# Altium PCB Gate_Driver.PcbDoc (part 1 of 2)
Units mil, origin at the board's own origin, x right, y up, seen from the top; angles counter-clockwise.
Board outline 1574.8 x 1574.8 mil, 2 copper layers (Top Layer, Bottom Layer), stack 62 mil thick; 111 components, 52 nets, 273 pads, 84 vias.
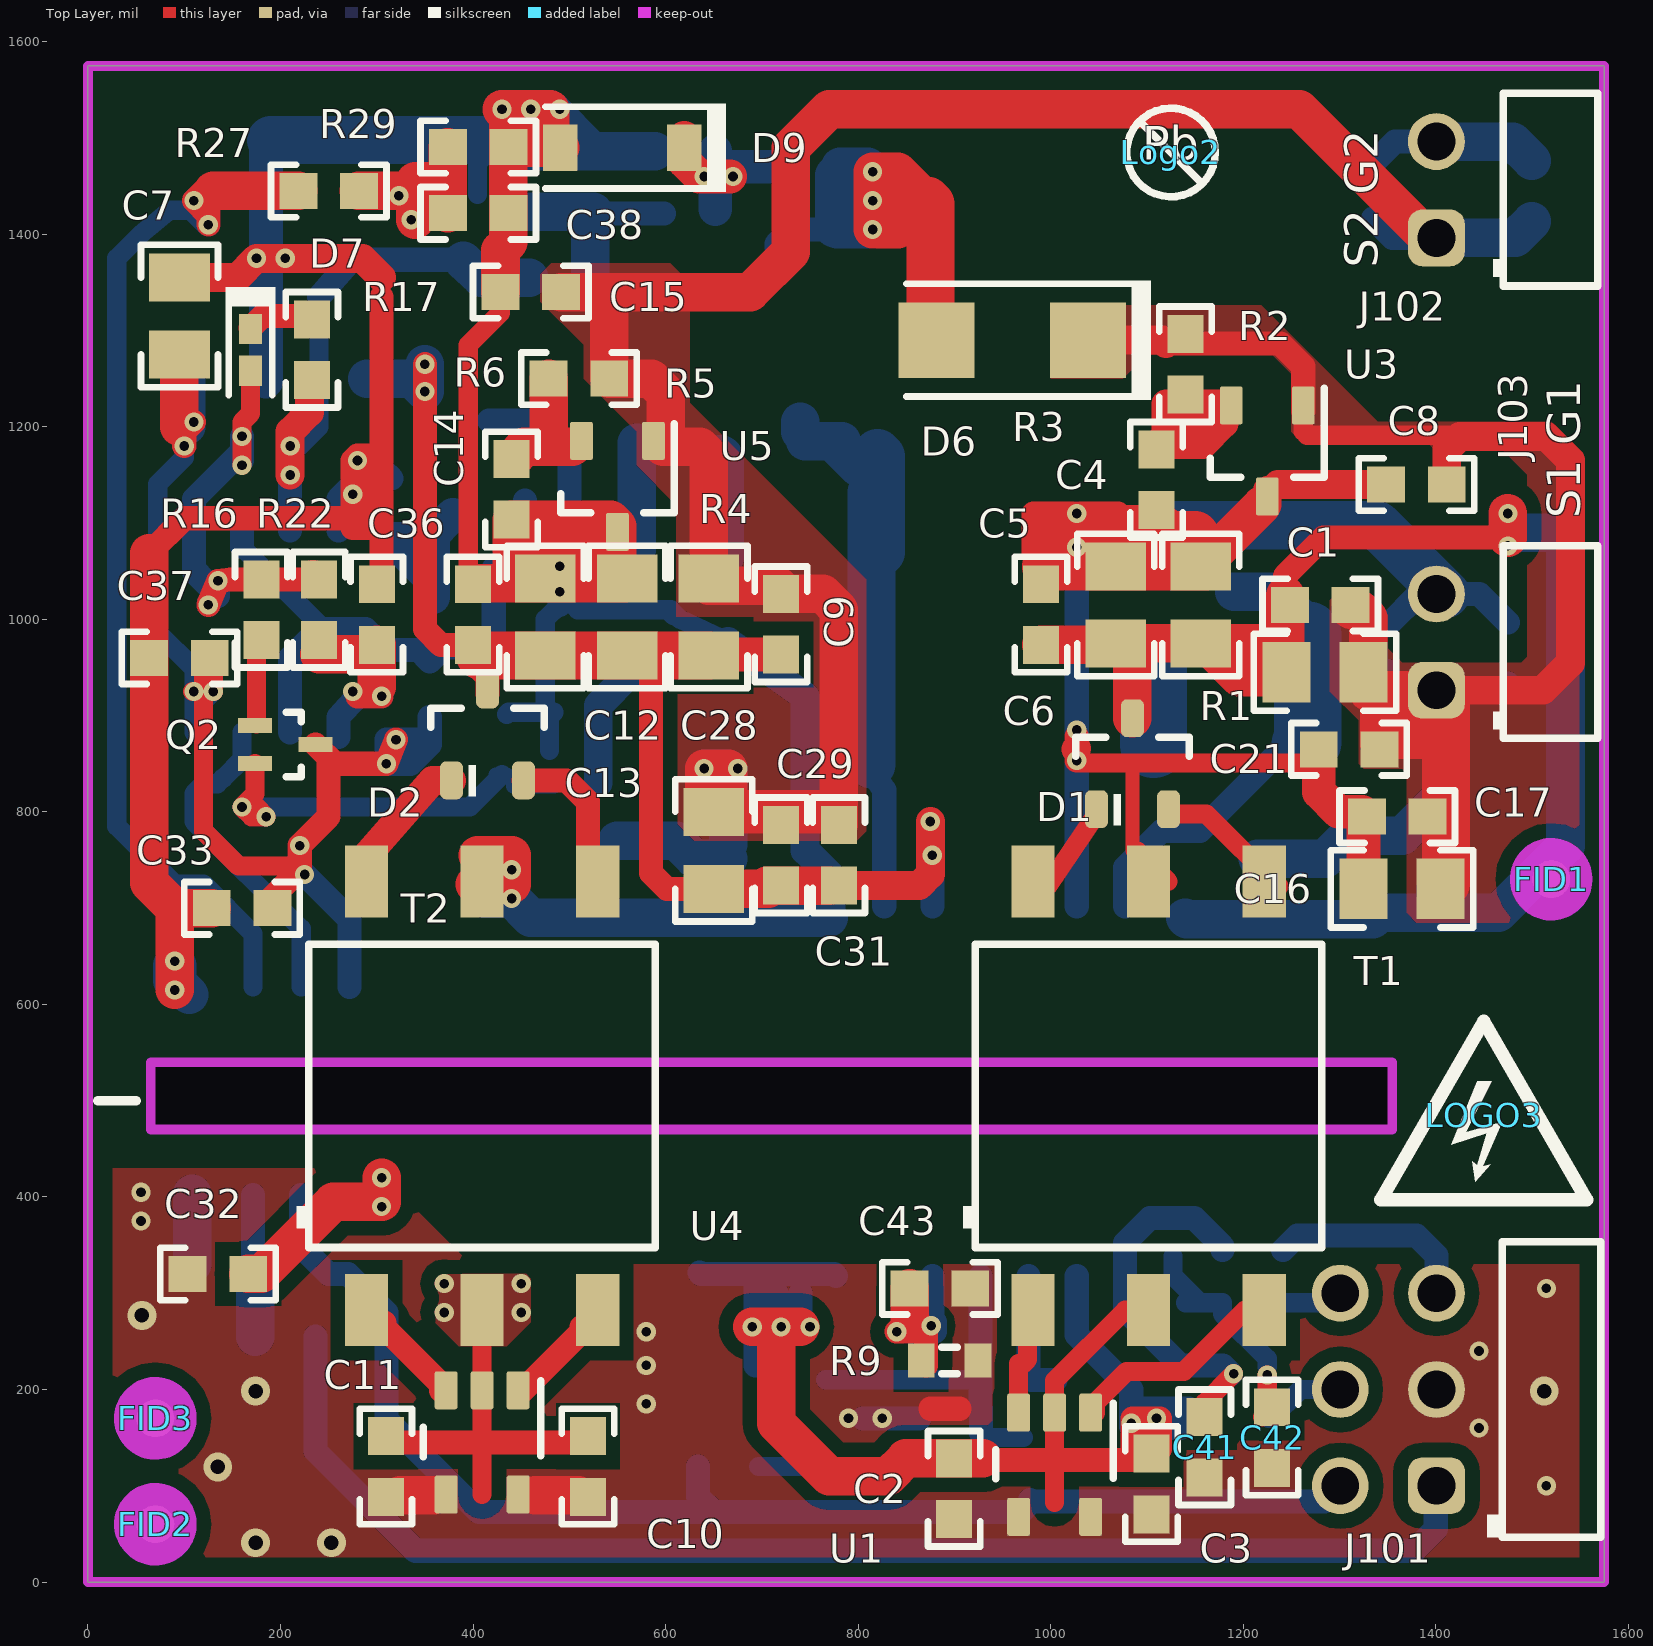
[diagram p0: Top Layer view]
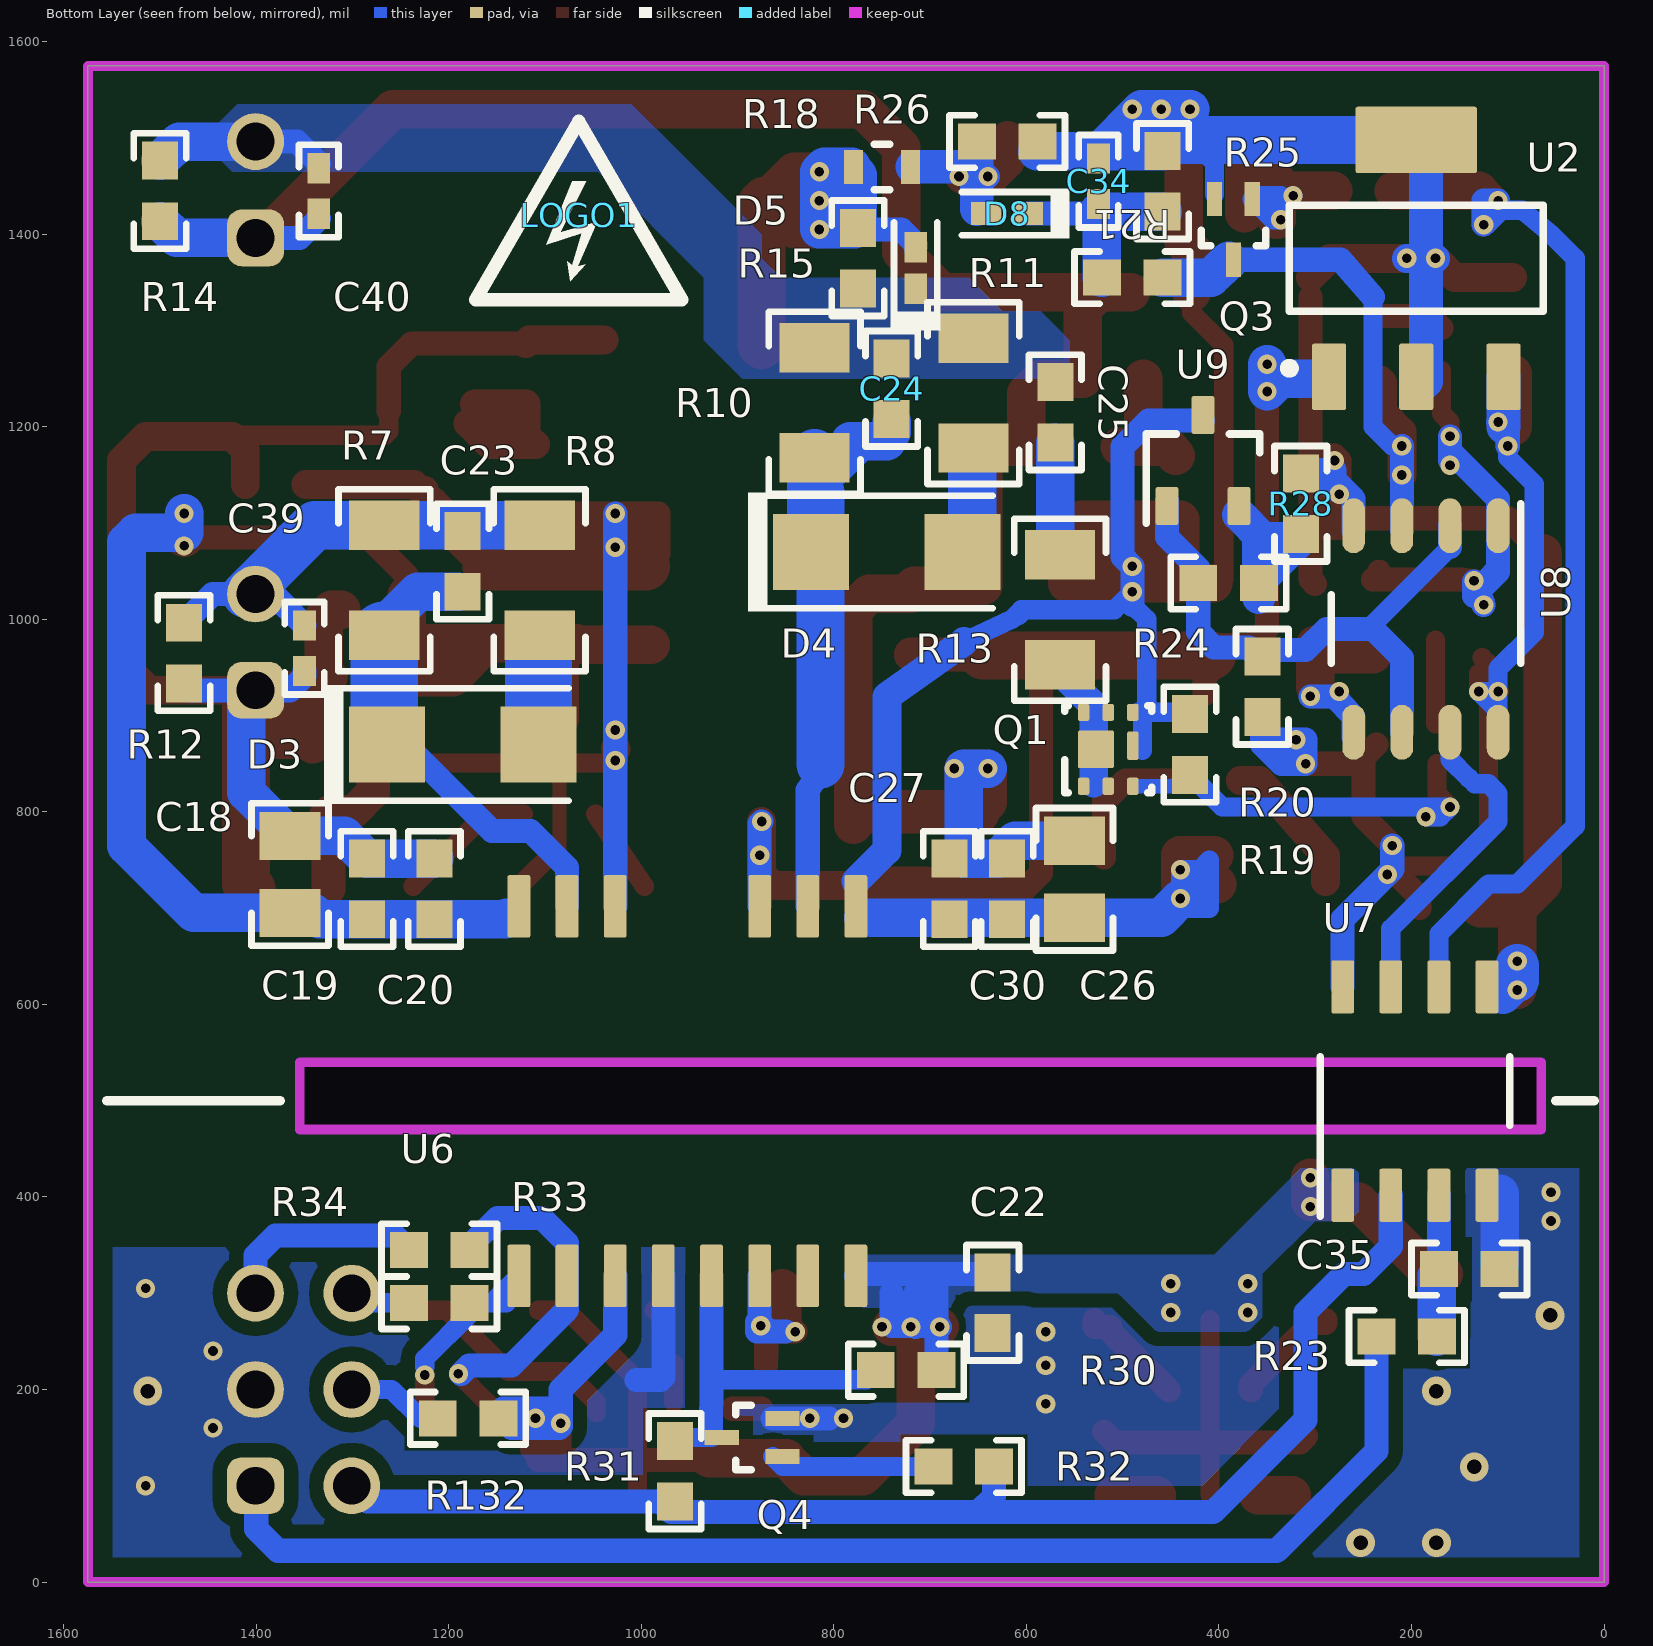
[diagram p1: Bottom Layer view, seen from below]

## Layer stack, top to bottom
Top Solder: solder mask 0.4, Solder Resist, Dk 3.5
Top Layer: signal copper 1.4
Dielectric 1: core 59.2, FR-4, Dk 4.8
Bottom Layer: signal copper 1.4
Bottom Solder: solder mask 0.4, Solder Resist, Dk 3.5

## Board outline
0,0 1574.8,0 1574.8,1574.8 0,1574.8
cut-out: 65,540 1355,540 1355,470 65,470

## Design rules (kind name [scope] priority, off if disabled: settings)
AcuteAngle [All] p1: minimum=3.00000000000000E+0001 checktracksonly=FALSE
AssemblyTestPointUsage [All] p1: valid=2
BoardOutlineClearance BoardOutlineClearance_MountingHoles [OnCopper and InComponentClass('Mounting Holes')] p1: gap=40 ignorepadtopadclearanceinfootprint=FALSE
BoardOutlineClearance BoardOutlineClearance_Poly [OnCopper and IsPoly] p2: gap=25 ignorepadtopadclearanceinfootprint=FALSE
BoardOutlineClearance [OnCopper and Not InComponentClass('Logo') and not InComponentClass('FiducialMark') and not InRegion(1000,500,4000,800) and not InPoly] p3: gap=0 ignorepadtopadclearanceinfootprint=FALSE
Clearance Clearance_Keepouts [((IsTrack Or IsArc) And Not InPoly) And IsFree and IsKeepOut vs ((IsTrack Or IsArc) And Not InPoly) And IsFree and IsKeepOut] p1: gap=0 ignorepadtopadclearanceinfootprint=FALSE
Clearance Clearance_Poly [InPolygon] p2: gap=15 ignorepadtopadclearanceinfootprint=FALSE
Clearance Clearance_FiducialMark [IsKeepOut and InComponentClass('FiducialMark') vs IsPad and InComponentClass('FiducialMark')] p3: gap=0 ignorepadtopadclearanceinfootprint=FALSE
Clearance [All vs not InComponent('D7')and not InComponent('Q1') and not InComponent('D8')and not InComponent('D5') and not InComponent('U4')and not InComponent('U1')] p4: gap=15 ignorepadtopadclearanceinfootprint=FALSE
ComponentClearance ComponentClearance_MountingHoles_FiducialMarks [InComponentClass('Mounting Holes') vs InComponentClass('FiducialMark')] p1: gap=50 collisioncheckmode=3 verticalgap=10 showdistances=FALSE
ComponentClearance ComponentClearance_Shunt [InComponentClass('Header') vs InComponentClass('Shunt')] p2: gap=0 collisioncheckmode=3 verticalgap=0 showdistances=FALSE
ComponentClearance ComponentClearance_Logo [InComponentClass('Logo')] p3: gap=50 collisioncheckmode=3 verticalgap=10 showdistances=FALSE
ComponentClearance ComponentClearance_ScrewToNut [(HasFootprint('NY PMS 440 0025 PH')) vs (HasFootprint('Keystone_1902C'))] p4: gap=5 collisioncheckmode=3 verticalgap=10 showdistances=FALSE
ComponentClearance ComponentClearance_MountingHoles [InComponentClass('Mounting Holes')] p5: gap=250 collisioncheckmode=3 verticalgap=100000 showdistances=FALSE
ComponentClearance ComponentClearance_SmallPassives [HasFootprint('0201*') or HasFootprint('0402*') or HasFootprint('0508') or HasFootprint('0603*') or HasFootprint('0612') or HasFootprint('0805*') or HasFootprint('0815*') or HasFootprint('0830*') or HasFootprint('1206*') or HasFootprint('1210*') or HasFootprint('1808*') or HasFootprint('1812*') or HasFootprint('1825*') or HasFootprint('2010*') or HasFootprint('2220*') or HasFootprint('2225*') or HasFootprint('2512*') or HasFootprint('2728*') or HasFootprint('3518*') vs HasFootprint('0201*') or HasFootprint('0402*') or HasFootprint('0508') or HasFootprint('0603*') or HasFootprint('0612') or HasFootprint('0805*') or HasFootprint('0815*') or HasFootprint('0830*') or HasFootprint('1206*') or HasFootprint('1210*') or HasFootprint('1808*') or HasFootprint('1812*') or HasFootprint('1825*') or HasFootprint('2010*') or HasFootprint('2220*') or HasFootprint('2225*') or HasFootprint('2512*') or HasFootprint('2728*') or HasFootprint('3518*')] p6: gap=14.96 collisioncheckmode=3 verticalgap=10 showdistances=FALSE
ComponentClearance ComponentClearance_THtoSMT [IsThruComponent vs IsSMTComponent] p7: gap=27.56 collisioncheckmode=3 verticalgap=30 showdistances=FALSE
ComponentClearance ComponentClearance_THtoTH [IsThruComponent vs IsThruComponent] p8: gap=30 collisioncheckmode=3 verticalgap=30 showdistances=FALSE
ComponentClearance [All] p9: gap=19.68 collisioncheckmode=3 verticalgap=10 showdistances=FALSE
DiffPairsRouting [All] p1: maxlimit=100 minlimit=10 mostfreqgap=10 toplayer_minwidth=15 toplayer_maxwidth=15 toplayer_prefwidth=15 bottomlayer_minwidth=15 bottomlayer_maxwidth=15 bottomlayer_prefwidth=15 maxuncoupledlength=1000
FabricationTestPointUsage TestPointUsage [All] p1: valid=2 allowmultiple=FALSE
FabricationTestpoint Testpoint [All] p1: side=3 testpointundercomponent=TRUE minsize=40 maxsize=100 preferedsize=60 minholesize=0 maxholesize=40 preferedholesize=32 testpointgrid=1 allowsidetop=TRUE allowsidebottom=TRUE usegrid=TRUE gridtolerance=0.01
FanoutControl Fanout_LCC [IsLCC] p1: bgadir=Out bgaviamode=Centered fanoutstyle=Auto fanoutdirection=Alternating viagrid=1 // Fanout_LCC (Default Rule)
FanoutControl Fanout_BGA [IsBGA] p2: bgadir=Out bgaviamode=Centered fanoutstyle=Auto fanoutdirection=Alternating viagrid=1 // Fanout_BGA (Default Rule)
FanoutControl Fanout_Default [All] p4: bgadir=Out bgaviamode=Centered fanoutstyle=Auto fanoutdirection=Alternating viagrid=1 // Fanout_Default (Default Rule)
FanoutControl Fanout_Small [(CompPinCount < 5)] p5: bgadir=Out bgaviamode=Centered fanoutstyle=Auto fanoutdirection=OutThenIn viagrid=1 // Fanout_Small (Default Rule)
HoleSize [All] p1: absolutevalues=TRUE maxlimit=251 minlimit=7.87 maxpercent=80.000 minpercent=20.000
MinimumAnnularRing MinimumAnnularRing_ThermalPadVias [IsVia and InAnyComponent] p1: minimumring=5.91
MinimumAnnularRing [All] p2: minimumring=5
MinimumSolderMaskSliver MinimumSolderMaskSliver_Logo [InComponentClass('Logo') vs InComponentClass('Logo')] p1: minsoldermaskwidth=0.7
MinimumSolderMaskSliver [All] p2: minsoldermaskwidth=2
PlaneConnect [All] p1: planeconnectstyle=Relief reliefexpansion=10 reliefentries=4 reliefconductorwidth=10 reliefairgap=10
PolygonConnect [All] p1: connectstyle=Direct reliefconductorwidth=10 reliefentries=4 polygonreliefangle="90 Angle" airgapwidth=10
RoutingVias ThermalPadVias [IsVia and InAnyComponent] p1: holewidth=7.87 width=19.68 viastyle="Through Hole" minholewidth=7.87 minwidth=19.68 maxholewidth=12.99 maxwidth=23.62
RoutingVias [All] p2: holewidth=16 width=34 viastyle="Through Hole" minholewidth=7.87 minwidth=20 maxholewidth=40 maxwidth=65
SilkToBoardRegionClearance [Not ((IsComment or IsDesignator) And (Hide <> 'False')) and not InRegion(1000,500,4000,800)] p1:
SilkToSilkClearance SilkToSilkClearance_Pb-FreeLogo [(HasFootprint('Pb-Free_Overlay_Medium') OR HasFootprint('Pb-Free_Overlay_Small')) vs (HasFootprint('Pb-Free_Overlay_Medium') OR HasFootprint('Pb-Free_Overlay_Small'))] p1: silktosilkclearance=0
SilkToSilkClearance [All] p2: silktosilkclearance=4
SilkToSolderMaskClearance SilkToComponentPadClearance [(IsPad or IsFill or IsRegion) and InAnycomponent] p1: minsilkscreentomaskgap=0 clearancetoexposedcopper=TRUE
SilkToSolderMaskClearance "Silk to Solder Mask Opening" [All] p2: minsilkscreentomaskgap=0 clearancetoexposedcopper=FALSE
SolderMaskExpansion [All] p1: expansion=1.97
Width [All] p1: maxlimit=100 minlimit=6 preferedwidth=10 checkconnectedcopper=TRUE
15 further rules are at their usual default settings.

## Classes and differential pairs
component class FiducialMark: FID1 FID2 FID3
component class Gate_Driver_Hardware: !PCB FID1 FID2 FID3 LOGO1 Logo2 LOGO3
component class Gate_Driver: C1 C2 C3 C4 C5 C6 C7 C8 C9 C10 C11 C12 C13 C14 C15 C16 C17 C18 C19 C20 C21 C22 C23 C24 C25 C26 C27 C28 C29 C30 C31 C32 C33 C34 C35 C36 C37 C38 C39 C40 C41 C42 C43 D1 D2 D3 D4 D5 D6 D7 D8 D9 J101 J102 J103 Q1 Q2 Q3 Q4 R1 R2 R3 R4 R5 R6 R7 R8 R9 R10 R11 R12 R13 R14 R15 R16 R17 R18 R19 R20 R21 R22 R23 R24 R25 R26 R27 R28 R29 R30 R31 R32 R33 R34 R132 T1 T2 U1 U2 U3 U4 U5 U6 U7 U8 U9
component class Header: J101 J102 J103

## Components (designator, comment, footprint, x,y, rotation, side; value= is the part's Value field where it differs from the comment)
C1 "CGA3E2X7R1E104K080AA" 0603 1280,1015 r0 top value=0.1uF
C2 "GRT188C81A106ME13D" 0603 899.69,96.81 r270 top value=10uF
C3 "CGA3E2X7R1E104K080AA" 0603 1104.69,101.81 r270 top value=0.1uF
C4 "GRT21BR61H475KE13L" 0805_HV 1067.6,1015 r90 top value=4.7uF
C5 "GRT21BR61H475KE13L" 0805_HV 1155.83,1015 r90 top value=4.7uF
C6 "CGA3E2X7R1E104K080AA" 0603 990,1005 r90 top value=0.1uF
C7 "GRT21BR61H475KE13L" 0805_HV 95,1315 r90 top value=4.7uF
C8 "CGA3E2X7R1E104K080AA" 0603 1380,1140 r180 top value=0.1uF
C9 "CGA3E2X7R1E104K080AA" 0603 720,995 r90 top value=0.1uF
C10 "GRT188C81A106ME13D" 0603 519.37,120 r270 top value=10uF
C11 "CGA3E2X7R1E104K080AA" 0603 309.37,120 r270 top value=0.1uF
C12 "GRT21BR61H475KE13L" 0805_HV 560,1002.44 r90 top value=4.7uF
C13 "GRT21BR61H475KE13L" 0805_HV 475,1002.44 r90 top value=4.7uF
C14 "CGA3E2X7R1E104K080AA" 0603 400,1005 r90 top value=0.1uF
C15 "CGA3E2X7R1E104K080AA" 0603 460,1340 r180 top value=0.1uF
C16 "GRT21BR61H475KE13L" 0805_HV 1365,720 r180 top value=4.7uF
C17 "CGA3E2X7R1E104K080AA" 0603 1360,795 r180 top value=0.1uF
C18 "GRT21BR61H475KE13L" 0805_HV 1365,735 r270 bottom value=4.7uF
C19 "CGA3E2X7R1E104K080AA" 0603 1285,720 r270 bottom value=0.1uF
C20 "CGA3E2C0G1H103J080AA" 0603 1215,720 r270 bottom value=0.01uF
C21 "CGA3E2C0G1H103J080AA" 0603 1310,865 r180 top value=0.01uF
C22 "CGA3E2X7R1E104K080AA" 0603 635,290 r270 bottom value=0.1uF
C23 "CGA3E2X7R1E104K080AA" 0603 1185.55,1060.18 r90 bottom value=0.1uF
C24 "CGA3E2X7R1E104K080AA" 0603 740,1239.51 r90 bottom value=0.1uF
C25 "CGA3E2X7R1E104K080AA" 0603 570,1215 r270 bottom value=0.1uF
C26 "GRT21BR61H475KE13L" 0805_HV 550,730 r90 bottom value=4.7uF
C27 "CGA3E2X7R1E104K080AA" 0603 680,720 r90 bottom value=0.1uF
C28 "GRT21BR61H475KE13L" 0805_HV 650,760 r90 top value=4.7uF
C29 "CGA3E2X7R1E104K080AA" 0603 720,755 r90 top value=0.1uF
C30 "CGA3E2C0G1H103J080AA" 0603 620,720 r90 bottom value=0.01uF
C31 "CGA3E2C0G1H103J080AA" 0603 780,755 r90 top value=0.01uF
C32 "CGA3E2X7R1E104K080AA" 0603 135,320 r180 top value=0.1uF
C33 "CGA3E2X7R1E104K080AA" 0603 160,700 r180 top value=0.1uF
C34 "GRM1555C1H270JA01D" 0402 525,1455 r90 bottom value=27pF
C35 "CGA3E2NP01H101J080AA" 0603 140,325 r180 bottom value=100pF
C36 "GCM1885C1H471JA16D" 0603 300,1005 r90 top value=470pF
C37 "CGA3E2X7R1E104K080AA" 0603 95,960 r180 top value=0.1uF
C38 "GCM1885C2A101JA16D" 0603 405.28,1421.89 r0 top value=100pF
C39 "GCM155R71H102KA37D" 0402 1350,970 r270 bottom value=1000pF
C40 "GCM155R71H102KA37D" 0402 1335,1445 r270 bottom value=1000pF
C41 "GCM1885C2A101JA16D" 0603 1160,140 r270 top value=100pF
C42 "GCM1885C2A101JA16D" 0603 1230,150 r270 top value=100pF
C43 "GCM1885C2A101JA16D" 0603 885,305 r0 top value=100pF
D1 "BAV70-E3-08" SOT-23 1085,850 r90 top value=70V
D2 "BAV70-E3-08" SOT-23 415,880 r90 top value=70V
D3 "MBRA340T3G" SMA 1185.55,870 r180 bottom value=40V
D4 "MBRA340T3G" SMA 745,1070 r180 bottom value=40V
D5 "1N4148X-TP" SOD-523 715,1365 r90 bottom value=75V
D6 "BYG23T-M3/TR" SMA 960,1290 r180 top value=1300V
D7 "1N4148X-TP" SOD-523 168.8,1280 r270 top value=75V
D8 "1N4148X-TP" SOD-523 620,1421.46 r0 bottom value=75V
D9 "BZT52C5V1-G3-08" SOD-123 555,1490 r180 top value=5.1V
FID1 "Fiducial" Fiducial10-20 1520,730 r0 top
FID2 "Fiducial" Fiducial10-20 70,60 r0 top
FID3 "Fiducial" Fiducial10-20 70,170 r0 top
J101 "90122-0763" Molex_90122-0763 1350.82,200 r180 top
J102 "90121-0762" Molex_90121-0762 1400.63,1446.3 r180 top
J103 "90121-0762" Molex_90121-0762 1400.63,976.3 r180 top
LOGO1 "DANGER HIGH VOLTAGE" IEC_HighVoltage_Small 1065,1420 r180 bottom
Logo2 "Pb-Free Symbol" Pb-Free_Overlay_Small 1125,1485 r0 top
LOGO3 "DANGER HIGH VOLTAGE" IEC_HighVoltage_Small 1450,485 r0 top
Q1 "CSD17313Q2" DQK0006C 515,865 r90 bottom value=30V
Q2 "MMBT3904T-7-F" SOT-523 205,870 r0 top value="40 V"
Q3 "MMBT3904T-7-F" SOT-523 385,1405 r270 bottom value="40 V"
Q4 "MMBT3904T-7-F" SOT-523 885,150 r0 bottom value="40 V"
R1 "CRCW08054K70JNEA" 0805_HV 1285,945 r180 top value=4.7k
R2 "RT0603DRE073K01L" 0603 1140,1265 r90 top value=3.01k
R3 "RT0603DRE074K99L" 0603 1110,1145 r90 top value=4.99k
R4 "CRCW08054K70JNEA" 0805_HV 645,1002.44 r270 top value=4.7k
R5 "RT0603DRE073K01L" 0603 510,1250 r0 top value=3.01k
R6 "RT0603DRE074K99L" 0603 440,1135 r90 top value=4.99k
R7 "CRCW12065R11FKEA" 1206 1267.05,1040.67 r90 bottom value=5.11
R8 "CRM1206-JW-1R0ELF" 1206 1105.55,1040.67 r90 bottom value=1.0
R9 "1" J1-0603 895,230 r0 top
R10 "CRCW12065R11FKEA" 1206 820,1225 r90 bottom value=5.11
R11 "CRM1206-JW-1R0ELF" 1206 655,1235 r90 bottom value=1.0
R12 "CRCW060310K0FKEA" 0603 1475,965 r90 bottom value=10.0k
R13 "CRCW120627R0JNEA" 1206 565,1010 r90 bottom value=27
R14 "CRCW060310K0FKEA" 0603 1500,1445 r90 bottom value=10.0k
R15 "RC0603JR-075K1L" 0603 775,1375 r270 bottom value=5.1k
R16 "RCA06031K00JNEA" 0603 180,1010 r270 top value=1.0k
R17 "RCA06031K00JNEA" 0603 232.5,1280 r270 top value=1.0k
R18 "TNPW060310K0BEEA" TNPW0603 750,1470 r0 bottom value=10.0k
R19 "RCA06031K00JNEA" 0603 430,869.96 r90 bottom value=1.0k
R20 "RC0603JR-075K1L" 0603 355,930 r270 bottom value=5.1k
R21 "CRCW06031K00FKEA" 0603 490,1355 r0 bottom value=1.00k
R22 "RC0603JR-072K2L" 0603 240,1010 r270 top value=2.2k
R23 "RC0603JR-075K1L" 0603 205,255 r180 bottom value=5.1k
R24 "RT0603DRE072KL" 0603 390,1037.8 r0 bottom value=2.00k
R25 "RC0603JR-075K1L" 0603 458.5,1455 r270 bottom value=5.1k
R26 "RC0603JR-075K1L" 0603 620,1496.46 r0 bottom value=5.1k
R27 "RCA06031K00JNEA" 0603 250,1445 r0 top value=1.0k
R28 "RT0603DRE0710KL" 0603 315,1120 r270 bottom value=10.0k
R29 "RC0603JR-0715KL" 0603 405.28,1490.59 r180 top value=15k
R30 "RC0603JR-075K1L" 0603 725,220 r180 bottom value=5.1k
R31 "CRCW06030000Z0EA" 0603 965,115 r90 bottom value=0
R32 "RC0603JR-075K1L" 0603 665,120 r180 bottom value=5.1k
R33 "CRCW06030000Z0EA" 0603 1210,290 r0 bottom value=0
R34 "CRCW06030000Z0EA" 0603 1210,345 r0 bottom value=0
R132 "CRCW06030000Z0EA" 0603 1180,170 r180 bottom value=0
T1 "3.9:1" Wurth_750342879 1101.77,505 r90 top value=50uH
T2 "3.9:1" Wurth_750342879 409.37,505 r90 top value=50uH
U1 "SN6501QDBVRQ1" DBV0005A_N 1004.06,121.81 r270 top
U2 "TPS7B6950QDCYRQ1" DCY0004A_N 195,1375 r90 bottom
U3 "TL431AQDBZRQ1" DBZ0003A_N 1225,1175 r270 top
U4 "SN6501QDBVRQ1" DBV0005A_N 409.37,145 r270 top
U5 "TL431AQDBZRQ1" DBZ0003A_N 550,1138.07 r270 top
U6 "UCC21530QDWKRQ1" DWK0014A 952.13,510 r90 bottom
U7 "ISO7721QDRQ1" D0008B_HV 196.5,510 r90 bottom
U8 "LMV762QMA" D0008A_N 185,990 r270 bottom
U9 "TL431AQDBZRQ1" DBZ0003A_N 416.57,1165 r90 bottom

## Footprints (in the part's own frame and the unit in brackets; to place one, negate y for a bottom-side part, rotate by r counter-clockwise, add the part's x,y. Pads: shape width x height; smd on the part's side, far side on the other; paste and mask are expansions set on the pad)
0402 [mm] "0402 from SM-752 data"
  rect 0.8x0.6 smd: 1(-0.6,0) 2(0.6,0)
  silkscreen extent -1.22,-0.52 1.22,0.52, body extent -0.55,-0.3 0.55,0.3, height 0.6
0603 [mm] "0603 from SM-752 data"
  rect 1x0.95 smd: 1(-0.8,0) 2(0.8,0)
  silkscreen extent -1.52,-0.69 1.52,0.69, body extent -0.87,-0.47 0.87,0.47, height 1
0805_HV [mil] "0805 with 30mil clearance between pads"
  rect 50x63 smd: 1(-40,0) 2(40,0)
  silkscreen extent -74,-40 74,40, body extent -43,-29 43,29, height 57
1206 [mm] "1206 from SM-752 data"
  rect 1.3x1.85 smd: 1(-1.45,0) 2(1.45,0)
  silkscreen extent -2.4,-1.21 2.4,1.21, body extent -1.7,-0.9 1.7,0.9, height 1.35
D0008A_N [mm] "SOIC, 8-Leads, Body 4.9x3.9mm, Pitch 1.27mm, IPC Medium Density"
  oval 1.45x0.6 smd: 1(-2.725,1.905) 2(-2.725,0.635) 3(-2.725,-0.635) 4(-2.725,-1.905) 5(2.725,-1.905) 6(2.725,-0.635) 7(2.725,0.635) 8(2.725,1.905)
  silkscreen extent -3.3,-2.5 0.9,2.5, body extent -3,-2.45 3,2.45, height 1.63
D0008B_HV [mm] "SOIC, 8-Leads, Body 4.9x3.9mm, Pitch 1.27mm, HV / Isolation option"
  rrect17% 1.4x0.6 smd: 1(-2.75,1.905) 2(-2.75,0.635) 3(-2.75,-0.635) 4(-2.75,-1.905) 5(2.75,-1.905) 6(2.75,-0.635) 7(2.75,0.635) 8(2.75,1.905)
  silkscreen extent -3.3,-2.5 0.9,2.5, body extent -3,-2.45 3,2.45, height 1.63
DBV0005A_N [mm] "SOT23, 5-Leads, Body 2.9x1.6mm, Pitch 0.95mm, Lead Span 2.8mm, IPC Medium Density"
  rrect17% 1x0.6 smd: 1(-1.375,0.95) 2(-1.375,0) 3(-1.375,-0.95) 4(1.375,-0.95) 5(1.375,0.95)
  silkscreen extent -1.63,-1.55 0.38,1.55, body extent -1.42,-1.46 1.42,1.46, height 1.09
DBZ0003A_N [mm] "SOT23, 3-Leads, Body 2.9x1.3mm, Pitch 0.95mm, Lead Span 2.4mm, IPC Medium Density"
  rrect17% 1x0.6 smd: 1(-1.2,0.95) 2(-1.2,-0.95) 3(1.2,0)
  silkscreen extent -1.65,-1.5 0.7,1.5, body extent -1.26,-1.46 1.26,1.46, height 0.98
DCY0004A_N [mm] "SOT223/SC73, 4-Leads, Body 6.5x3.5mm, Pitch 2.3mm, Lead Span 7mm, IPC Medium Density"
  rrect11% 1.75x0.9 smd: 1(-3.125,2.3) 2(-3.125,0) 3(-3.125,-2.3)
  rrect6% 1.75x3.2 smd: 4(3.125,0)
  silkscreen extent -3.02,-3.35 1.4,3.48, body extent -3.48,-3.25 3.48,3.25, height 1.68
DQK0006C [mm] "WSON"
  rrect12% 0.9x0.86 on Bottom Paste: 0(0,0.325)
  rrect34% 0.7x0.29 on Bottom Paste: 0(0.095,-0.65)
  rrect33% 0.45x0.3 smd: 1(-0.975,0.65) 2(-0.975,0) 3(-0.975,-0.65) 4(0.975,-0.65) 5(0.975,0) 6(0.975,0.65)
  rrect33% 0.75x0.3 smd paste-0.15: 7(0.095,-0.65)
  rrect11% 1x0.95 smd paste-0.5: 8(0,0.325)
  silkscreen extent -1.15,-1.15 1.15,1.15, body extent -1,-1 1,1, height 0.82
DWK0014A [mm] "SOIC-14"
  rrect17% 1.65x0.6 smd: 1(-4.875,4.445) 2(-4.875,3.175) 3(-4.875,1.905) 4(-4.875,0.635) 5(-4.875,-0.635) 6(-4.875,-1.905) 7(-4.875,-3.175) 8(-4.875,-4.445) 9(4.875,-4.445) 10(4.875,-3.175) 11(4.875,-1.905) 14(4.875,1.905) 15(4.875,3.175) 16(4.875,4.445)
  body extent -5.17,-5.15 5.17,5.15, height 2.59
Fiducial10-20 [mm]
  round 1 smd mask+0.5: 1(0,0)
  Top Layer keep-out circle w1.178: c0,0 r0.5
IEC_HighVoltage_Small [mil]
  silkscreen extent -107,-88 107,97
J1-0603 [mm] "Chip Resistor, Body 1.6x0.8mm, IPC High Density"
  rect 0.7x0.9 smd: 1(-0.75,0) 2(0.75,0)
  silkscreen extent -0.2,-0.35 0.2,0.35, body extent -0.85,-0.48 0.85,0.48, height 0.9
Molex_90121-0762 [mm] "Header, 2.54mm, 2x1, R/A, TH"
  rrect50% 1.5x1.5 hole 1: 1(0,1.27)
  round 1.5 hole 1: 2(0,-1.27)
  silkscreen extent -4.25,-2.54 -1.5,2.54, body extent -11.01,-2.54 0.31,2.54, height 3.6
Molex_90122-0763 [mm] "Header, 2.54mm, 3x2, R/A, TH"
  rrect50% 1.5x1.5 hole 1: 1(-1.27,2.54)
  round 1.5 hole 1: 2(1.27,2.54) 3(-1.27,0) 4(1.27,0) 5(-1.27,-2.54) 6(1.27,-2.54)
  silkscreen extent -5.6,-3.9 -2.6,3.9, body extent -12.27,-3.81 1.57,3.81, height 6.35
Pb-Free_Overlay_Small [mil]
  silkscreen extent -46,-46 46,46
SMA [mm] "Molded Diode, 2-Leads, Body 4.3x2.6mm, IPC Medium Density, based on OnSemi component dimensions and land pattern"
  rect 2x2 smd: 1(-2,0) 2(2,0)
  silkscreen extent -3.66,-1.57 2.79,1.57, body extent -2.6,-1.3 2.6,1.3, height 2.42
SOD-123 [mm] "On Semi recommended land pattern"
  rect 0.915x1.22 smd: 1(-1.637,0) 2(1.637,0)
  silkscreen extent -2.74,-1.17 2.03,1.17, body extent -1.93,-0.9 1.93,0.9, height 1.35
SOD-523 [mm] "NXP Semiconductor recommended land pattern, nominal STEP model"
  rect 0.8x0.6 smd paste-0.05: 1(-0.55,0) 2(0.55,0)
  silkscreen extent -1.65,-0.66 1.2,0.66, body extent -0.8,-0.4 0.8,0.4, height 0.72
SOT-23 [mm] "SOT23, 3-Leads, Body 2.9x1.3mm, Pitch 0.95mm, Lead Span 2.5mm, IPC Medium Density"
  rrect50% 1x0.6 smd: 1(-1.2,0.95) 2(-1.2,-0.95) 3(1.2,0)
  silkscreen extent -1.63,-1.5 0.7,1.5, body extent -1.16,-1.45 1.21,1.45, height 1
SOT-523 [mm] "From Diodes Inc datasheet component parameters"
  rect 0.9x0.4 smd: 1(-0.8,0.5) 2(-0.8,-0.5) 3(0.8,0)
  silkscreen extent 0.02,-0.85 0.42,0.85, body extent -0.8,-0.8 0.8,0.8, height 0.79
TNPW0603 [mm] "Vishay"
  rect 0.5x0.9 smd: 1(-0.75,0) 2(0.75,0)
  silkscreen extent -0.2,-0.6 0.2,0.6, body extent -0.85,-0.47 0.85,0.47, height 0.55
Wurth_750342879 [mm] "SMD, 6-Leads, Body 9.14x8mm, Pitch 3.05mm"
  rect 1.9x1.14 smd: 1(-5.655,3.05) 2(-5.655,0) 3(-5.655,-3.05) 4(5.655,-3.05) 5(5.655,0) 6(5.655,3.05)
  silkscreen extent -4,-4.57 4,4.9, body extent -6.35,-4.57 6.35,4.57, height 7.83

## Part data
C1 C3 C6 C8 C9 C11 C14 C15 C17 C19 C22 C23 C24 C25 C27 C29 C32 C33 C37: "CAP, CERM, 0.1 礔, 25 V,+/- 10%, X7R, AEC-Q200 Grade 1, 0603", Cap_Case=0603, Manufacturer=TDK, Supplier Part Number 1=445-5667-1-ND, TempCo=X7R, Tolerance_%=10, Value2=25V, ValueDisplayed=0.1μF
C2 C10: "CAP, CERM, 10 礔, 10 V,+/- 20%, X6S, AEC-Q200 Grade 2, 0603", Cap_Case=0603, Manufacturer=MuRata, Supplier Part Number 1=490-12283-1-ND, TempCo=X6S, Tolerance_%=20, Value2=10V, ValueDisplayed=10μF
C4 C5 C7 C12 C13 C16 C18 C26 C28: "CAP, CERM, 4.7 礔, 50 V,+/- 10%, X5R, AEC-Q200 Grade 3, 0805", Cap_Case=0805, Manufacturer=MuRata, Supplier Part Number 1=490-12394-1-ND, TempCo=X5R, Tolerance_%=10, Value2=50V, ValueDisplayed=4.7μF
C20 C21 C30 C31: "CAP, CERM, 0.01 礔, 50 V,+/- 5%, C0G/NP0, AEC-Q200 Grade 1, 0603", Cap_Case=0603, Manufacturer=TDK, Supplier Part Number 1=445-6916-1-ND, TempCo=C0G/NP0, Tolerance_%=5, Value2=50V, ValueDisplayed=0.01μF
C34: "CAP, CERM, 27 pF, 50 V,+/- 5%, C0G/NP0, 0402", Cap_Case=0402, Manufacturer=MuRata, Supplier Part Number 1=14T3294, TempCo=C0G/NP0, Tolerance_%=5, Value2=50V, ValueDisplayed=27pF
C35: "CAP, CERM, 100 pF, 50 V,+/- 5%, C0G/NP0, AEC-Q200 Grade 0, 0603", Cap_Case=0603, Manufacturer=TDK, Supplier Part Number 1=445-12386-1-ND, TempCo=C0G/NP0, Tolerance_%=5, Value2=50V, ValueDisplayed=100pF
C36: "CAP, CERM, 470 pF, 50 V,+/- 5%, C0G/NP0, AEC-Q200 Grade 1, 0603", Cap_Case=0603, Manufacturer=MuRata, Supplier Part Number 1=490-4965-1-ND, TempCo=C0G/NP0, Tolerance_%=5, Value2=50V, ValueDisplayed=470pF
C38 C41 C42 C43: "CAP, CERM, 100 pF, 100 V,+/- 5%, C0G/NP0, AEC-Q200 Grade 1, 0603", Cap_Case=0603, Manufacturer=MuRata, Supplier Part Number 1=490-4771-1-ND, TempCo=C0G/NP0, Tolerance_%=5, Value2=100V, ValueDisplayed=100pF
C39 C40: "CAP, CERM, 1000 pF, 50 V,+/- 10%, X7R, AEC-Q200 Grade 1, 0402", Cap_Case=0402, Manufacturer=MuRata, Supplier Part Number 1=490-4761-1-ND, TempCo=X7R, Tolerance_%=10, Value2=50V, ValueDisplayed=1000pF
D1 D2: "Diode, Switching, 70 V, 0.25 A, AEC-Q101, SOT-23", Manufacturer=Vishay-Semiconductor, Supplier Part Number 1=BAV70-E3-08CT-ND, Value1=0.25A, Value2=1.25V
D3 D4: "Diode, Schottky, 40 V, 3 A, SMA", Manufacturer="ON Semiconductor", Supplier Part Number 1=1431078, Value1=3A, Value2=0.415V
D5 D7 D8: "Diode, Switching, 75 V, 0.3 A, SOD-523", Manufacturer="Micro Commercial Components", Supplier Part Number 1=1N4148XTPMSCT-ND, Value1=0.3A, Value2=1.25V
D6: library part CMP-0077058-1, "Diode, Ultrafast, 1300 V, 1 A, SMA", Manufacturer=Vishay-Semiconductor, Supplier Part Number 1=BYG23T-M3/CT-ND, Value1=1A, Value2=1.9V
D9: "Diode, Zener, 5.1 V, 500 mW, SOD-123", Manufacturer=Vishay-Semiconductor, Power_W=0.5, Supplier Part Number 1=BZT52C5V1-G3-08-ND, Value1=0.5W
FID1 FID2 FID3: "Fiducial mark.  There is nothing to buy or mount.", Manufacturer=N/A
J101: library part CMP-0077741-1, "Header, 2.54mm, 3x2, Gold, R/A, TH", Color=Black, Current_A=3A, Manufacturer=Molex, Supplier Part Number 1=WM50030-06-ND, Voltage_V=350V
J102 J103: library part CMP-0077745-1, "Header, 2.54mm, 2x1, Gold with Tin tail, R/A, TH", Color=Black, Current_A=3A, Manufacturer=Molex, Supplier Part Number 1=WM8108-ND, Voltage_V=350V
LOGO1 LOGO3: library part IEC_HighVoltage, "IEC 61010-1 High Voltage Warning"
Logo2: library part Pb-Free
Q1: "MOSFET, N-CH, 30 V, 5 A, DQK0006C (WSON-6)", Alternate Manufacturer=None, Manufacturer="Texas Instruments", Supplier Part Number 1=296-27233-1-ND, Value1="0.026 ohm", Value2="2.1 nC"
Q2 Q3 Q4: library part "MMBT3904T-7-F, Diodes Inc.", "Transistor, NPN, 40 V, 0.2 A, SOT-523", Manufacturer="Diodes Inc.", Supplier Part Number 1=MMBT3904T-FDICT-ND, Value1="0.2 A", Value2=300
R1 R4: "RES, 4.7 k, 5%, 0.125 W, 0805", Manufacturer=Vishay-Dale, Power_W=0.125, Supplier Part Number 1=541-4.7KACT-ND, TempCo="200 ppm/C", Tolerance_%=5, Value1=5%, Value2=0.125W, Value_Code=4k70, ValueDisplayed=4.7k
R2 R5: "RES, 3.01 k, 0.5%, 0.1 W, 0603", Manufacturer="Yageo America", Power_W=0.1, TempCo="50 ppm/C", Tolerance_%=0.5, Value1=0.5%, Value2=0.1W, Value_Code=3k01, ValueDisplayed=3.01k
R3 R6: "RES, 4.99 k, 0.5%, 0.1 W, 0603", Manufacturer="Yageo America", Power_W=0.1, TempCo="50 ppm/C", Tolerance_%=0.5, Value1=0.5%, Value2=0.1W, Value_Code=4k99, ValueDisplayed=4.99k
R7 R10: "RES, 5.11, 1%, 0.25 W, 1206", Manufacturer=Vishay-Dale, Power_W=0.25, Supplier Part Number 1=541-5.11FFCT-ND, TempCo="100 ppm/C", Tolerance_%=1, Value1=1%, Value2=0.25W, Value_Code=5R11, ValueDisplayed=5.11
R8 R11: "RES, 1.0, 5%, 0.5 W, 1206", Manufacturer=Bourns, Power_W=0.5, Supplier Part Number 1=652-CRM1206JW1R0ELF, TempCo="150 ppm/C", Tolerance_%=5, Value1=5%, Value2=0.5W, Value_Code=1R00, ValueDisplayed=1.0
R9: library part Res3, "Resistor"
R12 R14: "RES, 10.0 k, 1%, 0.1 W, 0603", Manufacturer=Vishay-Dale, Power_W=0.1, Supplier Part Number 1=541-10.0KHCT-ND, TempCo="100 ppm/C", Tolerance_%=1, Value1=1%, Value2=0.1W, Value_Code=10k0, ValueDisplayed=10.0k
R13: "RES, 27, 5%, 0.25 W, 1206", Manufacturer=Vishay-Dale, Power_W=0.25, Supplier Part Number 1=541-27ECT-ND, TempCo="200 ppm/C", Tolerance_%=5, Value1=5%, Value2=0.25W, Value_Code=27R0, ValueDisplayed=27
R15 R20 R23 R25 R26 R30 R32: "RES, 5.1 k, 5%, 0.1 W, 0603", Manufacturer="Yageo America", Power_W=0.1, Supplier Part Number 1=311-5.1KGRCT-ND, TempCo="100 ppm/C", Tolerance_%=5, Value1=5%, Value2=0.1W, Value_Code=5k10, ValueDisplayed=5.1k
R16 R17 R19 R27: "RES, 1.0 k, 5%, 0.1 W, AEC-Q200 Grade 0, 0603", Manufacturer=Vishay-Dale, Power_W=0.1, Supplier Part Number 1=541-2213-1-ND, TempCo="200 ppm/C", Tolerance_%=5, Value1=5%, Value2=0.1W, Value_Code=1k00, ValueDisplayed=1.0k
R18: "RES, 10.0 k, 0.1%, 0.1 W, AEC-Q200 Grade 1, 0603", Manufacturer=Vishay-Dale, Power_W=0.1, Supplier Part Number 1=TNP10.0KAACT-ND, TempCo="25 ppm/C", Value1=0.1%, Value2=0.1W, Value_Code=10k0, ValueDisplayed=10.0k
R21: "RES, 1.00 k, 1%, 0.1 W, 0603", Manufacturer=Vishay-Dale, Power_W=0.1, Supplier Part Number 1=541-1.00KHCT-ND, TempCo="100 ppm/C", Tolerance_%=1, Value1=1%, Value2=0.1W, Value_Code=1k00, ValueDisplayed=1.00k
R22: "RES, 2.2 k, 5%, 0.1 W, 0603", Manufacturer="Yageo America", Power_W=0.1, Supplier Part Number 1=311-2.2KGRCT-ND, TempCo="100 ppm/C", Tolerance_%=5, Value1=5%, Value2=0.1W, Value_Code=2k20, ValueDisplayed=2.2k
R24: "RES, 2.00 k, 0.5%, 0.1 W, 0603", Manufacturer="Yageo America", Power_W=0.1, TempCo="50 ppm/C", Tolerance_%=0.5, Value1=0.5%, Value2=0.1W, Value_Code=2k00, ValueDisplayed=2.00k
R28: "RES, 10.0 k, 0.5%, 0.1 W, 0603", Manufacturer="Yageo America", Power_W=0.1, Supplier Part Number 1=603-RT0603DRE0710KL, TempCo="50 ppm/C", Tolerance_%=0.5, Value1=0.5%, Value2=0.1W, Value_Code=10k0, ValueDisplayed=10.0k
R29: "RES, 15 k, 5%, 0.1 W, 0603", Manufacturer="Yageo America", Power_W=0.1, Supplier Part Number 1=311-15KGRCT-ND, TempCo="100 ppm/C", Tolerance_%=5, Value1=5%, Value2=0.1W, Value_Code=15k0, ValueDisplayed=15k
R31 R33 R34 R132: "RES, 0, 5%, 0.1 W, 0603", Manufacturer=Vishay-Dale, Power_W=0.1, Supplier Part Number 1=541-0.0GCT-ND, TempCo="200 ppm/C", Tolerance_%=5, Value1=5%, Value2=0.1W, Value_Code=0000, ValueDisplayed=0
T1 T2: library part 750342879, "Transformer, 50 uH, SMT", Manufacturer="Wurth Elektronik", PartNumber=750343725, ValueDisplayed=50μH
U1 U4: "Automotive Low-Noise 350 mA, 410 kHz Transformer Driver, DBV0005A (SOT-23-5)", Alternate Manufacturer="Texas Instruments"
U2: "Automotive High-Voltage Ultra-Low IQ Low-Dropout Regulator/Fixed 5-V Output Voltage, DCY0004A (SOT-223-4)", Alternate Manufacturer="Texas Instruments"
U3 U5 U9: "Automotive Catalog Adjustable Precision Shunt Regulator, 34 ppm / degC, 100 mA, -40 to 125 degC, 3-pin SOT-23 (DBZ), Green (RoHS & no Sb/Br)", Alternate Manufacturer="Texas Instruments", Alternate PartNumber=Equivalent, Rating=Automotive, Supplier Part Number 1=296-21853-2-ND, Temp Coeff(Typ)(ppm/ degree C)=34
U6: library part CMP-0083997-1, "4-A, 6-A, 5.7-kVRMS Isolated Dual-Channel Gate Driver with Enable, DWK0014A (SOIC-14)", Alternate Manufacturer="Texas Instruments", Alternate PartNumber=UCC21521CDW, PartNumber=UCC21520QDWRQ1
U7: library part CMP-0077719-1, "Automotive, High Speed, Robust EMC Reinforced Dual-Channel Digital Isolator, D0008B (SOIC-8)", Alternate Manufacturer="Texas Instruments"
U8: "Automotive Low Voltage, Precision Comparator with Push-Pull Output, D0008A", Alternate Manufacturer="Texas Instruments"

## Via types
v1: diameter 20, hole 10, Top Layer to Bottom Layer, 78 vias
v2: diameter 30, hole 15, Top Layer to Bottom Layer, 6 vias

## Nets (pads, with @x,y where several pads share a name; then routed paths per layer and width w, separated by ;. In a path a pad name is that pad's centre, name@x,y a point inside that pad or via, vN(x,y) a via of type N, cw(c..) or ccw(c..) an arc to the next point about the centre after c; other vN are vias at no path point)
5Vin: C2.1 C3.1 C10.1 C11.1 C22.1 C32.1 R30.2 R132.2 T1.2 T2.2 U1.2 U4.2 U6.3 U6.8 U7.1 | length 2304.8
  Top Layer w20: 409.37,90.87 409.37,145 U4.2@409.37,199.13 T2.2@409.37,272.36 ; 1004.06,82.68 U1.2@1004.06,175.94 1004.06,209.06 1077.36,282.36 ; T1.2@1082.36,282.36 T1.2@1106.77,282.36
  Top Layer w25: C11.1@309.37,151.5 315.87,145 409.37,145 507.87,145 C10.1@519.37,156.5 ; C2.1@901.18,126.81 954.06,126.81 1085,126.81 ; C3.1@1107.56,126.81 1085,126.81 ; C3.1@1107.56,131.81 1113.8,138.05 1113.8,170 v1@1100,170 ; 1085,126.81 1091.5,133.31 C3.1@1104.69,133.31 1100,137.99 v1@1100,170 ; 1085,126.81 1085,170 v1@1100,170
  Top Layer w40: C32.1@166.5,320 180,320 255,395 305,395 v1(305,420) ; v1(690,265) v1@715,265 ; v1@740,265 v1@715,265 ; 929.69,128.31 C2.1@899.69,128.31 849.69,128.31 831.38,110 770,110 715,165 v1@715,265
  Bottom Layer w25: C22.1@635,321.5 636.5,320 775.2,320 U6.8@777.13,318.07 ; v1(690,265) 691.2,266.2 v1@693.5,266.2 ; R30.2@693.5,225 v1@693.5,266.2 ; 693.5,311.5 v1@693.5,266.2 ; v1@715,265 v1@715,266.2 ; 715,300 v1@715,266.2 ; 740,300 740,266.2 v1@715,266.2 ; U6.3@1027.13,318.07 1027.13,256.55 1083.68,200 1083.68,180 ; R132.2@1143.5,180 R132.2@1133.92,180 ; v1@693.5,266.2 v1@715,266.2 ; 1083.68,180 1083.68,161.32 1085,160 1110,160 ; 1083.68,180 1110,180 ; 1110,160 1135,160 1133.92,161.08 R132.2@1133.92,180 ; 1110,160 1110,180 ; 1110,180 R132.2@1133.92,180
  other v1: 1083.68,165 1110,170 720,265 750,265 370,280 450,280 370,310 450,310 305,390
+15Va: C1.1 C4.1 C5.1 C6.1 C18.2 C19.2 C20.2 D1.3 R1.2 U6.16 | length 1632.7
  Top Layer w25: C1.1@1243.5,1025 1243.5,1045.2 1283.31,1085 v1@1475,1085
  Top Layer w40: C6.1@990,973.5 1066.1,973.5 C4.1@1067.6,975 C5.1@1160.83,975 ; D1.3@1085,897.24 C4.1@1085,975 ; C1.1@1243.5,1025 1243.5,980 ; v1@1475,1085 v1(1475,1110) ; C5.1@1160.83,975 1238.5,975 1243.5,980 ; C5.1@1160.83,975 1195.83,940 1245,940 1243.5,941.5 1243.5,980
  Bottom Layer w40: 1140,690 1141.5,688.5 C20.2@1215,688.5 C19.2@1285,688.5 1334.5,688.5 1341,695 C18.2@1365,695 1465,695 1534.8,764.8 1534.8,1080.2 1525,1090 1475,1090 ; 1475,1095 v1(1475,1110)
  other v1: 1475,1076.3
+15Vb: C9.1 C12.1 C13.1 C14.1 C28.1 C29.1 C31.1 D2.3 R4.2 U2.1 U6.11 | length 1469.8
  Top Layer w25: v1(350,1265) v1(350,1236.73) 350,990 366.5,973.5 C14.1@400,973.5 ; C14.1@400,968.5 400,955 D2.3@415,940 ; D2.3@415,922.24 C14.1@415,955 ; C12.1@585,950 585,736.46 601.46,720 C28.1@645,720
  Top Layer w30: C31.1@780,723.5 863.5,723.5 875,735 v1(875,790)
  Top Layer w35: R4.2@645,962.44 646.06,963.5 C9.1@720,963.5
  Top Layer w40: C28.1@645,720 C29.1@701.5,720 ; C29.1@706.5,720 C29.1@701.5,720 ; C31.1@770,723.5 705,723.5 C29.1@701.5,720
  Top Layer w50: C14.1@407.44,962.44 R4.2@645,962.44
  Bottom Layer w25: v1(875,790) 877.13,787.87 877.13,777.87 v1(877.13,755) U6.11@877.13,701.93
  Bottom Layer w40: U2.1@290,1250 349.21,1250 ; 339.76,1246.97 v1(350,1236.73) v1(350,1265)
-4Va: C4.2 C5.2 C6.2 C8.2 C16.2 C17.2 C21.2 R3.1 T1.5 U3.3 U6.14 | length 1744.2
  Top Layer w15: T1.5@1085,759.41 1085,850.85
  Top Layer w20: v1(1027.13,853.35) 1029.63,850.85 1085,850.85 C21.2@1272.66,850.85 ; T1.5@1090,759.41 T1.5@1121.77,727.64
  Top Layer w25: C6.2@995,1055 982.13,1067.87 982.13,1085 ; v1(1027.13,853.35) 1027.13,865.85 v1@1027.13,878.35 ; 1067.6,1087.76 1064.84,1085 982.13,1085 ; 1070,1110 982.13,1110 982.13,1085
  Top Layer w30: 1026.28,865 1027.13,865.85 ; C4.2@1067.6,1055 1067.6,1087.76 1067.6,1107.6 ; C5.2@1160.83,1055 C5.2@1160.83,1060 ; U3.3@1225,1118.66 U3.3@1225,1133.66 ; U3.3@1236.34,1140 C8.2@1348.5,1140
  Top Layer w35: C21.2@1278.5,860 1278.5,820.47 1298.98,800 C17.2@1323.5,800 ; C16.2@1325,720 1325,791.5 C17.2@1328.5,795
  Top Layer w40: C5.2@1155.83,1055 1160.83,1060 U3.3@1219.49,1118.66
  Top Layer w50: C6.2@995,1055 1014.29,1055 C4.2@1067.6,1055 C5.2@1155.83,1055 C5.2@1160.83,1055 ; 1082.6,1094 R3.1@1115,1094 ; 1100.35,1087.76 1150,1087.76
  Bottom Layer w25: U6.14@1027.13,701.93 v1(1027.13,853.35) v1(1027.13,885) 1027.13,1085 v1(1027.13,1110)
  other v1: 1027.13,1075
